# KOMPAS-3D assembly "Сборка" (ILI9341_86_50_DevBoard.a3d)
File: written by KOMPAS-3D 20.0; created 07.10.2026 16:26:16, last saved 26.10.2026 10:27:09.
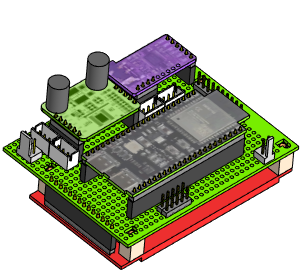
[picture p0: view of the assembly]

Document properties: Полное имя файла: D:\RicWork\Project-EPS32\box_compas\сборки компонентов\ILI9341_86_50_DevBoard.a3d

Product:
- Part/product: Сборка
    Масса: 0.245619
  - Component [assembly]: Сборка  | Масса: 0.132529; source file: макетка+модули.a3d
  - Component [assembly]: Сборка  | Масса: 0.11309; source file: ..\монитор\ILI9341_86_50 asm+.a3d

Referenced files in D:\RicWork\Project-EPS32\box_compas\монитор\: ILI9341_86_50 asm+.a3d
Referenced files in D:\RicWork\Project-EPS32\box_compas\сборки компонентов\: макетка+модули.a3d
